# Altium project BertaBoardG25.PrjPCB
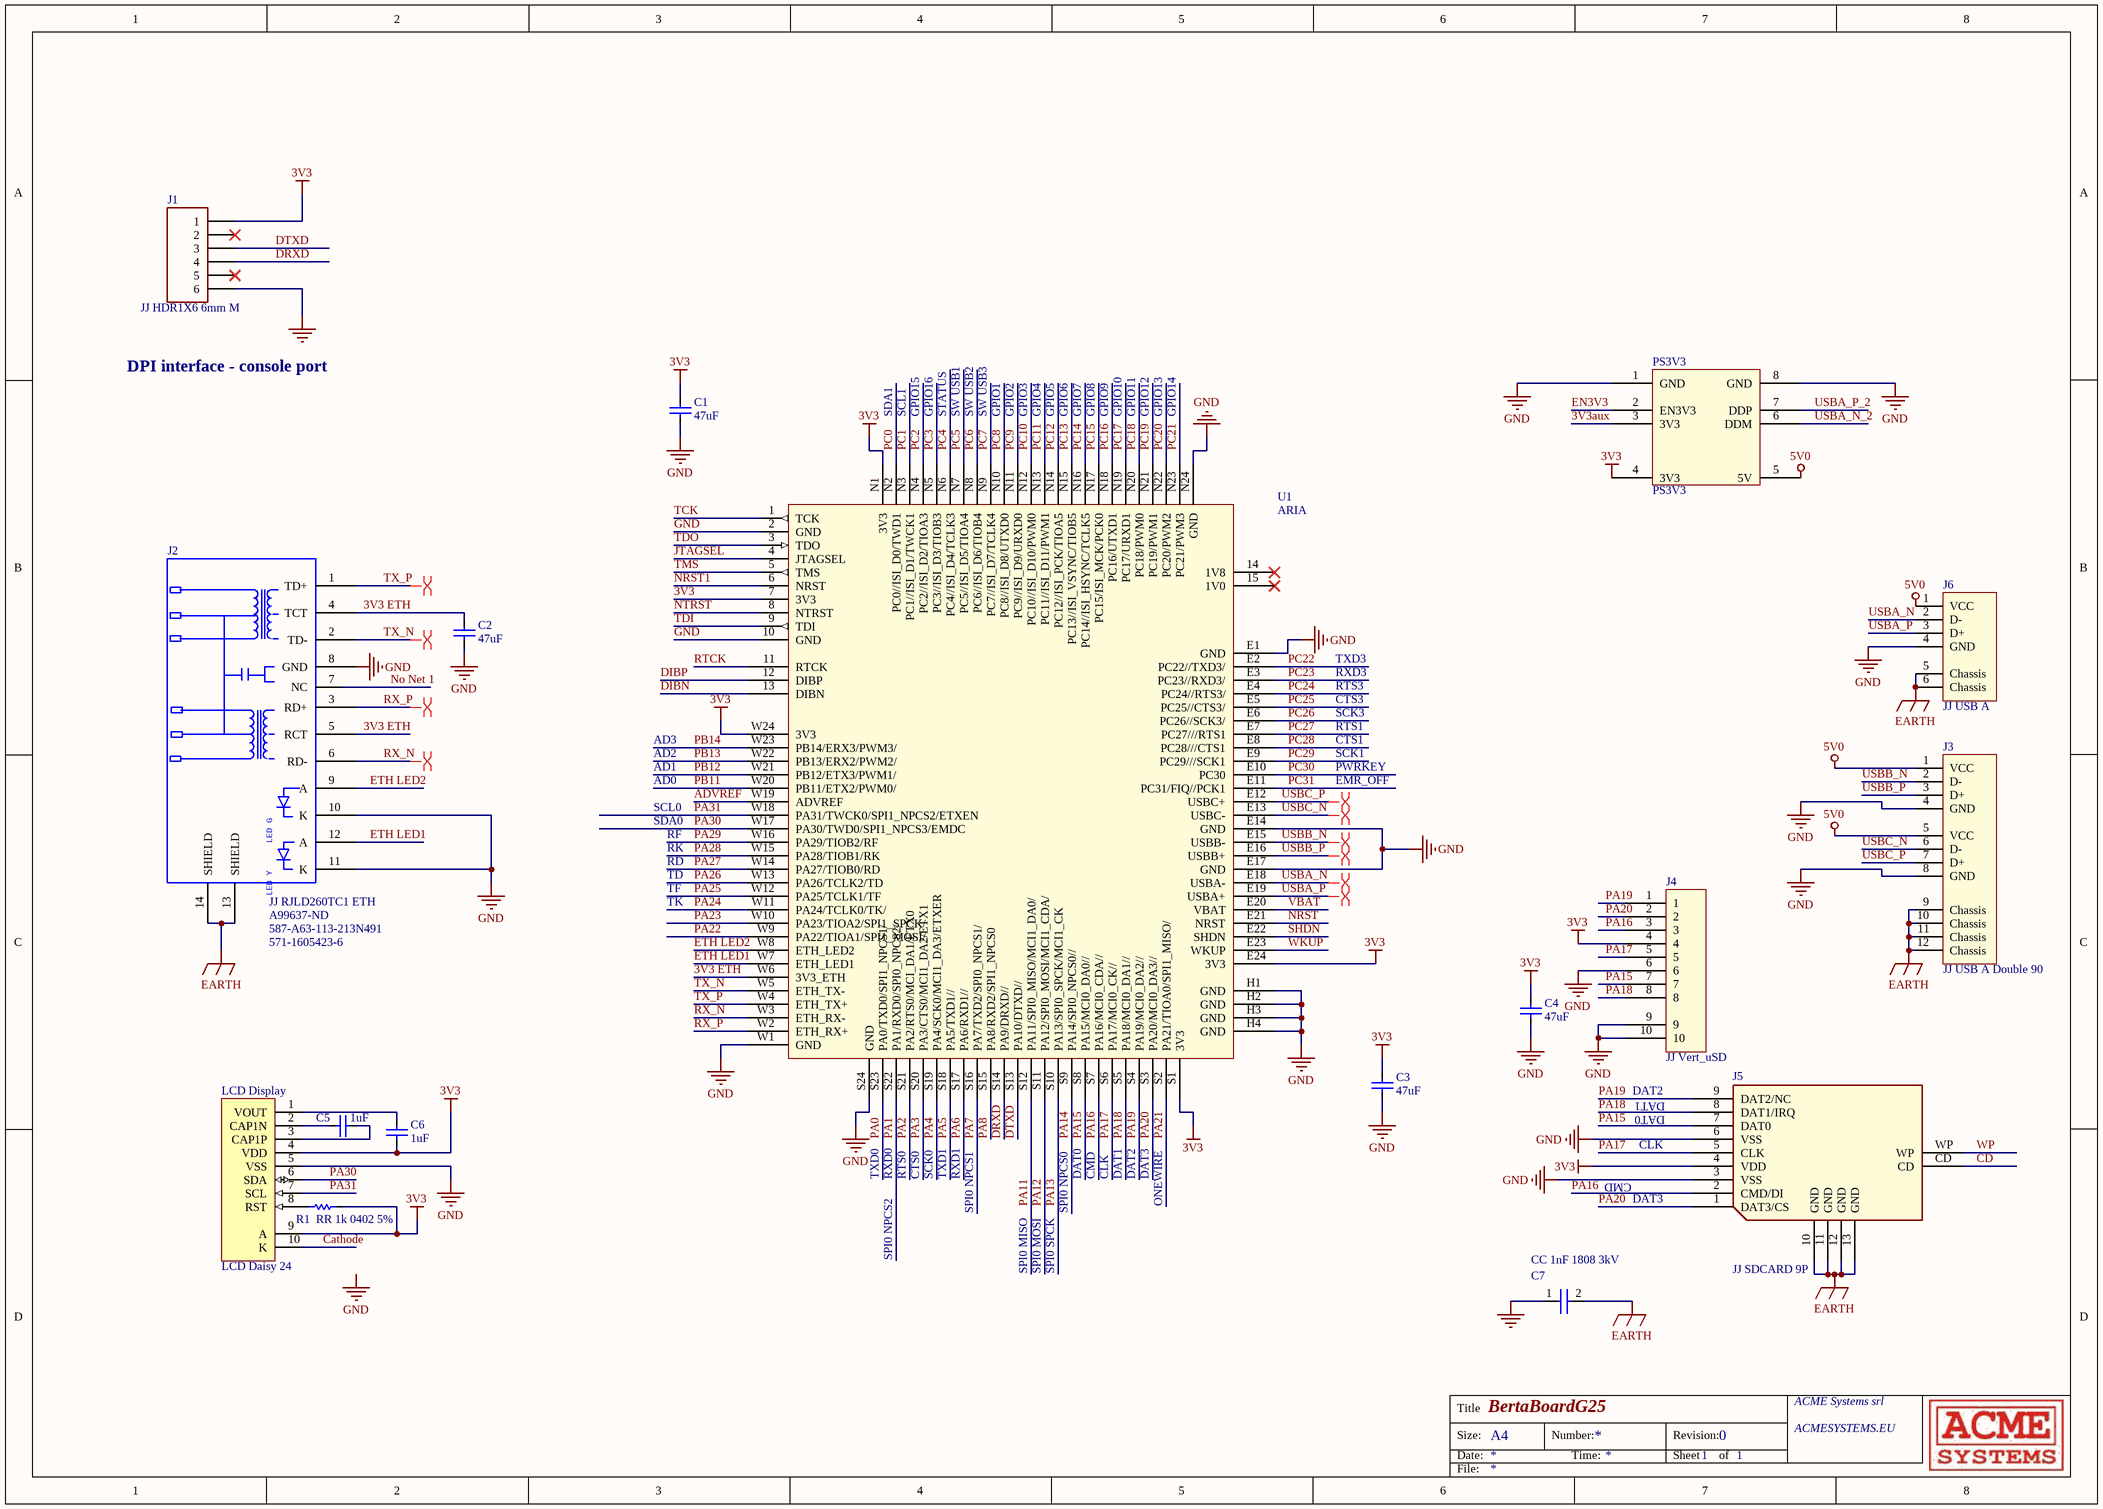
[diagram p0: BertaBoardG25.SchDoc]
1 sheet, 17 parts. Net scope: global (net labels, ports and power ports of the same name join across sheets).
Board file: BertaBoardG25.PcbDoc

## Sheet BertaBoardG25.SchDoc: BertaBoardG25
size A3; Organization: ACME Systems srl; Address2: ACMESYSTEMS.EU; Revision: 0; SheetNumber: 1; SheetTotal: 1

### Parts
C1  47uF  [CC 1206 (3216 metric)]
C2  47uF  [CC 1206 (3216 metric)]
C3  47uF  [CC 1206 (3216 metric)]
C4  47uF  [CC 1206 (3216 metric)]
C5  1uF  [CC 1206 (3216 metric)]
C6  1uF  [CC 1206 (3216 metric)]
C7  CC 1nF 1808 3kV  [CC 1808 (4520 metric)]
J1  JJ HDR1X6 6mm M  [HDR1X6 3D]
J2  JJ RJLD260TC1 ETH  Supplier Part Number 1: A99637-ND  Supplier Part Number 2: 587-A63-113-213N491  Supplier Part Number 3: 571-1605423-6  [RJLD-260TC1]
J3  JJ USB A Double 90  [USB2.0-double-FCI72309]
J4  JJ Vert_uSD  [JJ Vert_uSD]
J5  JJ SDCARD 9P  [JJ SDCARD 9P]
J6  JJ USB A  [USB2.0-Vert]
LCD_Display  LCD Daisy 24  [LCD Daisy24]
PS3V3  PS3V3  [AB PS3V3]
R1  RR 1k 0402 5%  [RR 0805 (2012 metric)]
U1  ARIA  [AB ARIA 2]

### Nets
3V3: C1.1 C3.1 C4.1 C6.2 J1.1 J4.4 J5.4(VDD) LCD_Display.4(VDD) LCD_Display.9(A) PS3V3.4(3V3) R1.2 U1.7(3V3) U1.E24(3V3) U1.N1(3V3) U1.S1(3V3) U1.W24(3V3)
5V0: J3.1(VCC) J3.5(VCC) J6.1(VCC) PS3V3.5(5V)
EARTH: C7.2 J2.13(SHIELD) J2.14(SHIELD) J3.9(Chassis) J3.10(Chassis) J3.11(Chassis) J3.12(Chassis) J5.10(GND) J5.11(GND) J5.12(GND) J5.13(GND) J6.5(Chassis) J6.6(Chassis)
GND: C1.2 C2.2 C3.2 C4.2 C7.1 J1.6 J2.8(GND) J2.10(K) J2.11(K) J3.4(GND) J3.8(GND) J4.6 J4.9 J4.10 J5.3(VSS) J5.6(VSS) J6.4(GND) LCD_Display.5(VSS) PS3V3.1(GND) PS3V3.8(GND) U1.2(GND) U1.10(GND) U1.E1(GND) U1.E14(GND) U1.E17(GND) U1.H1(GND) U1.H2(GND) U1.H3(GND) U1.H4(GND) U1.N24(GND) U1.S24(GND) U1.W1(GND)
3V3 ETH: C2.1 J2.4(TCT) J2.5(RCT) U1.W6(3V3_ETH)
3V3aux: PS3V3.3(3V3)
ADVREF: U1.W19(ADVREF)
Cathode: LCD_Display.10(K)
CD: J5.CD
DIBN: U1.13(DIBN)
DIBP: U1.12(DIBP)
DRXD: J1.4 U1.S14(PA9/DRXD//)
DTXD: J1.3 U1.S13(PA10/DTXD//)
EN3V3: PS3V3.2(EN3V3)
ETH LED1: J2.12(A) U1.W7(ETH_LED1)
ETH LED2: J2.9(A) U1.W8(ETH_LED2)
JTAGSEL: U1.4(JTAGSEL)
No Net 1: J2.7(NC)
NRST: U1.E21(NRST)
NRST1: U1.6(NRST)
NTRST: U1.8(NTRST)
PA0: U1.S23(PA0/TXD0/SPI1_NPCS1/)
PA1: U1.S22(PA1/RXD0/SPI0_NPCS2/)
PA2: U1.S21(PA2/RTS0/MCI_DA1/ETX0)
PA3: U1.S20(PA3/CTS0/MCI1_DA2/ETX1)
PA4: U1.S19(PA4/SCK0/MCI1_DA3/ETXER)
PA5: U1.S18(PA5/TXD1//)
PA6: U1.S17(PA6/RXD1//)
PA7: U1.S16(PA7/TXD2/SPI0_NPCS1/)
PA8: U1.S15(PA8/RXD2/SPI1_NPCS0)
PA11: U1.S12(PA11/SPI0_MISO/MCI1_DA0/)
PA12: U1.S11(PA12/SPI0_MOSI/MCI1_CDA/)
PA13: U1.S10(PA13/SPI0_SPCK/MCI1_CK)
PA14: U1.S9(PA14/SPI0_NPCS0//)
PA15: J4.7 J5.7(DAT0) U1.S8(PA15/MCI0_DA0//)
PA16: J4.3 J5.2(CMD/DI) U1.S7(PA16/MCI0_CDA//)
PA17: J4.5 J5.5(CLK) U1.S6(PA17/MCI0_CK//)
PA18: J4.8 J5.8(DAT1/IRQ) U1.S5(PA18/MCI0_DA1//)
PA19: J4.1 J5.9(DAT2/NC) U1.S4(PA19/MCI0_DA2//)
PA20: J4.2 J5.1(DAT3/CS) U1.S3(PA20/MCI0_DA3//)
PA21: U1.S2(PA21/TIOA0/SPI1_MISO/)
PA22: U1.W9(PA22/TIOA1/SPI1_MOSI/)
PA23: U1.W10(PA23/TIOA2/SPI1_SPCK/)
PA24: U1.W11(PA24/TCLK0/TK/)
PA25: U1.W12(PA25/TCLK1/TF)
PA26: U1.W13(PA26/TCLK2/TD)
PA27: U1.W14(PA27/TIOB0/RD)
PA28: U1.W15(PA28/TIOB1/RK)
PA29: U1.W16(PA29/TIOB2/RF)
PA30: LCD_Display.6(SDA) U1.W17(PA30/TWD0/SPI1_NPCS3/EMDC)
PA31: LCD_Display.7(SCL) U1.W18(PA31/TWCK0/SPI1_NPCS2/ETXEN)
PB11: U1.W20(PB11/ETX2/PWM0/)
PB12: U1.W21(PB12/ETX3/PWM1/)
PB13: U1.W22(PB13/ERX2/PWM2/)
PB14: U1.W23(PB14/ERX3/PWM3/)
PC0: U1.N2(PC0//ISI_D0/TWD1)
PC1: U1.N3(PC1//ISI_D1/TWCK1)
PC2: U1.N4(PC2//ISI_D2/TIOA3)
PC3: U1.N5(PC3//ISI_D3/TIOB3)
PC4: U1.N6(PC4//ISI_D4/TCLK3)
PC5: U1.N7(PC5//ISI_D5/TIOA4)
PC6: U1.N8(PC6//ISI_D6/TIOB4)
PC7: U1.N9(PC7//ISI_D7/TCLK4)
PC8: U1.N10(PC8//ISI_D8/UTXD0)
PC9: U1.N11(PC9//ISI_D9/URXD0)
PC10: U1.N12(PC10//ISI_D10/PWM0)
PC11: U1.N13(PC11//ISI_D11/PWM1)
PC12: U1.N14(PC12//ISI_PCK/TIOA5)
PC13: U1.N15(PC13//ISI_VSYNC/TIOB5)
PC14: U1.N16(PC14//ISI_HSYNC/TCLK5)
PC15: U1.N17(PC15/ISI_MCK/PCK0)
PC16: U1.N18(PC16/UTXD1)
PC17: U1.N19(PC17/URXD1)
PC18: U1.N20(PC18/PWM0)
PC19: U1.N21(PC19/PWM1)
PC20: U1.N22(PC20/PWM2)
PC21: U1.N23(PC21/PWM3)
PC22: U1.E2(PC22//TXD3/)
PC23: U1.E3(PC23//RXD3/)
PC24: U1.E4(PC24//RTS3/)
PC25: U1.E5(PC25//CTS3/)
PC26: U1.E6(PC26//SCK3/)
PC27: U1.E7(PC27///RTS1)
PC28: U1.E8(PC28///CTS1)
PC29: U1.E9(PC29///SCK1)
PC30: U1.E10(PC30)
PC31: U1.E11(PC31/FIQ//PCK1)
RTCK: U1.11(RTCK)
RX_N: J2.6(RD-) U1.W3(ETH_RX-)
RX_P: J2.3(RD+) U1.W2(ETH_RX+)
SHDN: U1.E22(SHDN)
TCK: U1.1(TCK)
TDI: U1.9(TDI)
TDO: U1.3(TDO)
TMS: U1.5(TMS)
TX_N: J2.2(TD-) U1.W5(ETH_TX-)
TX_P: J2.1(TD+) U1.W4(ETH_TX+)
USBA_N: J6.2(D-) U1.E18(USBA-)
USBA_N_2: PS3V3.6(DDM)
USBA_P: J6.3(D+) U1.E19(USBA+)
USBA_P_2: PS3V3.7(DDP)
USBB_N: J3.2(D-) U1.E15(USBB-)
USBB_P: J3.3(D+) U1.E16(USBB+)
USBC_N: J3.6(D-) U1.E13(USBC-)
USBC_P: J3.7(D+) U1.E12(USBC+)
VBAT: U1.E20(VBAT)
WKUP: U1.E23(WKUP)
WP: J5.WP
NetC5_1: C5.1 LCD_Display.2(CAP1N)
NetC5_2: C5.2 LCD_Display.3(CAP1P)
NetC6_1: C6.1 LCD_Display.1(VOUT)
NetLCD_Display_8: LCD_Display.8(RST) R1.1

Not connected (* = marked no-connect by the designer): J1 2* 5*; U1 14(1V8)* 15(1V0)*

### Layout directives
differential pair: RX_N, RX_P, TX_N, TX_P, USBA_N, USBA_P, USBB_N, USBB_P, USBC_N, USBC_P

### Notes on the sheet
- DPI interface - console port
- SDA1
- SCL1
- GPIO15
- GPIO16
- STATUS
- SW USB1
- SW USB2
- SW USB3
- GPIO1
- GPIO2
- GPIO3
- GPIO4
- GPIO5
- GPIO6
- GPIO7
- GPIO8
- GPIO9
- GPIO10
- GPIO11
- GPIO12
- GPIO13
- GPIO14
- TXD3
- RXD3
- RTS3
- CTS3
- SCK3
- AD3
- AD2
- AD1
- AD0
- SCK1
- RTS1
- CTS1
- PWRKEY
- EMR_OFF
- SCL0
- SDA0
- RF
- RK
- RD
- TD
- TF
- TK
- (near J4) DAT2
- DAT0
- DAT1
- TXD0
- RXD0
- RTS0
- CTS0
- SCK0
- TXD1
- RXD1
- CMD
- CLK
- DAT2
- DAT3
- SPI0 NPCS2
- SPI0 NPCS1
- SPI0 NPCS0
- ONEWIRE
- SPI0 MISO
- SPI0 MOSI
- SPI0 SPCK
- Labels drawn without touching a wire or pin: GND

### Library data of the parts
C1-C6 = CC Ceramic: Capacitor, Multi Layer Ceramic
C7 = CAP NP: Right: 20; Bottom: 10
J1 = Header 6: Header, 6-Pin
J2 = JJ RJLD260TC1 ETH: ETH connector RJLD-260TC1 TAIMAG; Right: 100; Bottom: 240
J3 = JJ USB A Double 90: USB2.0 Double type A connector; Right: 30; Bottom: 70
J6 = JJ USB A: USB 2.0 type A; Right: 30; Bottom: 70
LCD_Display = LCD Daisy 24: EZL display
PS3V3 = AB PS3V3
R1 = RR Resistor: Resistor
